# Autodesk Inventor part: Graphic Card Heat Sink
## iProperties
Company: Autodesk Inc.
Created: 2005-12
Part Number: Graphic Card Heat Sink
Document SubType Name: Modeling
Designer: Autodesk Inc.
Density: 1 g/cm^3
Author: Autodesk Inc.
Title: Personal Computer
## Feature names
1. Extrusion1
2. Extrusion3
3. Rectangular Pattern2
4. Extrusion4
5. Extrusion5
6. Rectangular Pattern3
